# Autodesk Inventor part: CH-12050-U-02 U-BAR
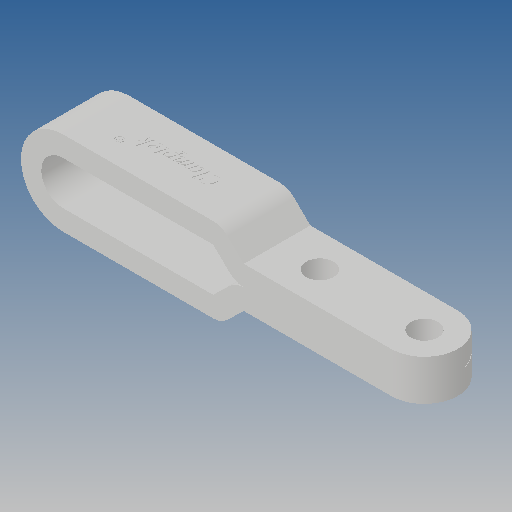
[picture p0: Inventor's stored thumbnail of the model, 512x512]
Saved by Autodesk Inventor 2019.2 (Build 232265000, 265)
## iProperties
Created: 2015-08
Part Number: CH-12050-U-02 U-BAR
Material: Ogólny
Document SubType Name: Modeling
Designer: CADENGINEERING4
Density: 1 g/cm^3
Appearance: Domyślna
Author: CADENGINEERING4
Revision Number: ÈÎºÎ
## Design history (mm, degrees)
feature "ÇÐ³ý-À­Éì2"
feature "ÇÐ³ý-À­Éì4"
node "Bryła1"
node "Bryła2"
